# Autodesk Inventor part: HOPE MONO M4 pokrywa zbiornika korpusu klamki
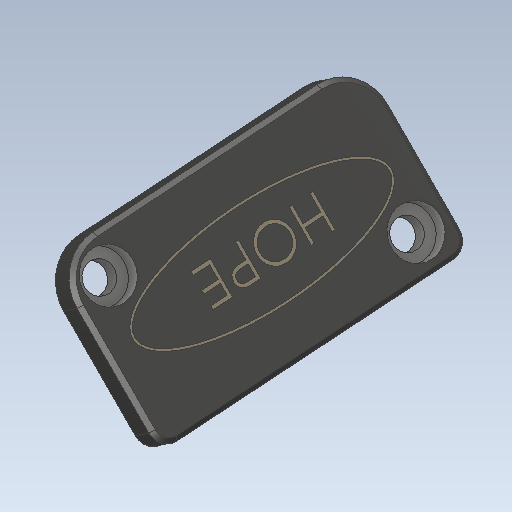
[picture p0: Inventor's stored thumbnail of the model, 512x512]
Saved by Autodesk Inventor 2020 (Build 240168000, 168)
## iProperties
Created: 2015-11
Part Number: HOPE MONO M4 pokrywa zbiornika korpusu klamki
Material: Ogólny
Document SubType Name: Modeling
Designer: Tomasz
Density: 1 g/cm^3
Appearance: Domyślna
Sending System: SolidWorks 2017
Last Author: Tomasz
Last Saved: 2017-11-19
Author: Tomasz
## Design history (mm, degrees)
feature "Imported1"
node "Bryła1"
